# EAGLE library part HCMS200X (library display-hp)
LED DISPLAY 4-character dot matrix
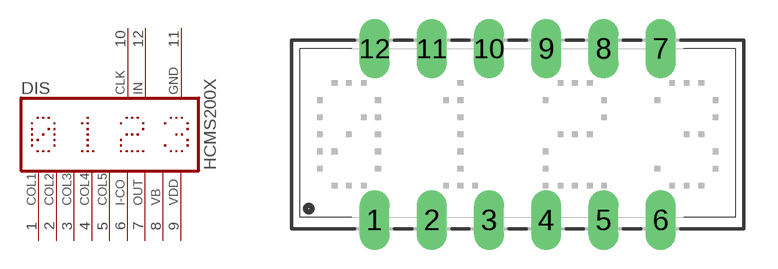
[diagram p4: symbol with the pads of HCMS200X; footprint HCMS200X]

Designator prefix DIS

## HCMS200X (OC_FARNELL: unknown; OC_NEWARK: unknown)  [HCMS200X]
1  COL1  in
2  COL2  in
3  COL3  in
4  COL4  in
5  COL5  in
6  I-CO  in
7  OUT  in
8  VB  in
9  VDD  pwr
10  CLK  in
11  GND  pwr
12  IN  in

## Footprint HCMS200X (pad centres in mm)
LED DISPLAY 5-mm 4 character dot matrix
drill 0.813 long: 1 -6.35,-3.81; 2 -3.81,-3.81; 3 -1.27,-3.81; 4 1.27,-3.81; 5 3.81,-3.81; 6 6.35,-3.81; 7 6.35,3.81; 8 3.81,3.81; 9 1.27,3.81; 10 -1.27,3.81; 11 -3.81,3.81; 12 -6.35,3.81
